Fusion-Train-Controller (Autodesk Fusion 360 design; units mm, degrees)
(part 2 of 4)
sketch "M4 preload adjuster" plane through (0, 0, 37.9) normal (0, 0, 1) x axis (1, 0, 0)
  circle C1 centre (12, -55) radius 2.2
extrude "Extrude6" cut sketch "M4 preload adjuster" along normal blind 14.2
work_plane "WorkPlane7" AlongDistance 37.9 ExtraOffset 0
sketch "Spring-side loaded retained M4 nut" plane through (0, 0, 37.9) normal (0, 0, 1) x axis (1, 0, 0)
  line L1 (14.1362, -51.3) -> (16.2724, -55)
  line L2 (9.8638, -51.3) -> (14.1362, -51.3)
  line L3 (7.7276, -55) -> (9.8638, -51.3)
  line L4 (9.8638, -58.7) -> (7.7276, -55)
  line L5 (14.1362, -58.7) -> (9.8638, -58.7)
  line L6 (16.2724, -55) -> (14.1362, -58.7)
extrude "Extrude7" cut sketch "Spring-side loaded retained M4 nut" along normal blind 3.5
work_plane "WorkPlane8" AlongDistance 37.9 ExtraOffset 0
sketch "Spring cup guide bolts" plane through (0, 0, 37.9) normal (0, 0, 1) x axis (1, 0, 0)
  circle C1 centre (5, -55) radius 1.7
extrude "Extrude8" cut sketch "Spring cup guide bolts" along normal blind 14.2
work_plane "WorkPlane9" AlongDistance 37.9 ExtraOffset 0
sketch "Spring cup guide bolts (1)" plane through (0, 0, 37.9) normal (0, 0, 1) x axis (1, 0, 0)
  circle C1 centre (19, -55) radius 1.7
extrude "Extrude9" cut sketch "Spring cup guide bolts (1)" along normal blind 14.2
work_plane "WorkPlane1" AlongDistance 1.5 ExtraOffset 0
sketch "Spring seat" plane through (1.5, 0, 0) normal (1, 0, 0) x axis (0, 0, -1)
  line L1 (-35, -49) -> (-35, -61)
  line L2 (-37, -49) -> (-35, -49)
  line L3 (-37, -61) -> (-37, -49)
  line L4 (-35, -61) -> (-37, -61)
extrude "Extrude1" new body sketch "Spring seat" along normal blind 21 bodies "P14 Captive spring cup"
work_plane "WorkPlane2" AlongDistance 27 ExtraOffset 0
sketch "Spring centering pilot" plane through (0, 0, 27) normal (0, 0, 1) x axis (1, 0, 0)
  circle C1 centre (12, -55) radius 2
extrude "Extrude2" add sketch "Spring centering pilot" along normal blind 8
work_plane "WorkPlane3" AlongDistance 34.9 ExtraOffset 0
sketch "Sliding guide clearance" plane through (0, 0, 34.9) normal (0, 0, 1) x axis (1, 0, 0)
  circle C1 centre (5, -55) radius 1.8
extrude "Extrude3" cut sketch "Sliding guide clearance" along normal blind 2.2
work_plane "WorkPlane4" AlongDistance 34.9 ExtraOffset 0
sketch "Sliding guide clearance (1)" plane through (0, 0, 34.9) normal (0, 0, 1) x axis (1, 0, 0)
  circle C1 centre (19, -55) radius 1.8
extrude "Extrude4" cut sketch "Sliding guide clearance (1)" along normal blind 2.2
work_plane "WorkPlane11" AlongDistance -18 ExtraOffset 0
sketch "Dedicated thick stop lug" plane through (-18, 0, 0) normal (1, 0, 0) x axis (0, 0, -1)
  line L1 (-72, 5) -> (-72, -5)
  line L2 (-95, 5) -> (-72, 5)
  line L3 (-95, -5) -> (-95, 5)
  line L4 (-72, -5) -> (-95, -5)
extrude "Extrude11" add sketch "Dedicated thick stop lug" along normal blind 11.5
work_plane "WorkPlane12" AlongDistance -18 ExtraOffset 0
sketch "Rounded stop contact" plane through (-18, 0, 0) normal (1, 0, 0) x axis (0, 0, -1)
  circle C1 centre (-95, 0) radius 5
extrude "Extrude12" add sketch "Rounded stop contact" along normal blind 11.5
work_plane "WorkPlane10" AlongDistance -36 ExtraOffset 0
sketch "Broad stop support ear" plane through (-36, 0, 0) normal (1, 0, 0) x axis (0, 0, -1)
  line L1 (-60, -20) -> (-60, -44)
  line L2 (-90, -20) -> (-60, -20)
  line L3 (-90, -44) -> (-90, -20)
  line L4 (-60, -44) -> (-90, -44)
extrude "Extrude10" add sketch "Broad stop support ear" along normal blind 12
work_plane "WorkPlane11" AlongDistance -24 ExtraOffset 0
sketch "Integrated steel-core end stop" plane through (-24, 0, 0) normal (1, 0, 0) x axis (0, 0, -1)
  circle C1 centre (-79.6754, -33.9652) radius 6
extrude "Extrude11" add sketch "Integrated steel-core end stop" along normal blind 15
work_plane "WorkPlane12" AlongDistance -36.1 ExtraOffset 0
sketch "M5 stop reinforcement bolt" plane through (-36.1, 0, 0) normal (1, 0, 0) x axis (0, 0, -1)
  circle C1 centre (-79.6754, -33.9652) radius 2.7
extrude "Extrude12" cut sketch "M5 stop reinforcement bolt" along normal blind 27.2
work_plane "WorkPlane13" AlongDistance -15.4 ExtraOffset 0
sketch "M5 captive stop nut" plane through (-15.4, 0, 0) normal (1, 0, 0) x axis (0, 0, -1)
  line L1 (-83.8754, -31.5403) -> (-79.6754, -29.1154)
  line L2 (-83.8754, -36.39) -> (-83.8754, -31.5403)
  line L3 (-79.6754, -38.8149) -> (-83.8754, -36.39)
  line L4 (-75.4754, -36.39) -> (-79.6754, -38.8149)
  line L5 (-75.4754, -31.5403) -> (-75.4754, -36.39)
  line L6 (-79.6754, -29.1154) -> (-75.4754, -31.5403)
extrude "Extrude13" cut sketch "M5 captive stop nut" along normal blind 6.5
work_plane "WorkPlane14" AlongDistance -36 ExtraOffset 0
sketch "Broad stop support ear (1)" plane through (-36, 0, 0) normal (1, 0, 0) x axis (0, 0, -1)
  line L1 (-60, 44) -> (-60, 20)
  line L2 (-90, 44) -> (-60, 44)
  line L3 (-90, 20) -> (-90, 44)
  line L4 (-60, 20) -> (-90, 20)
extrude "Extrude14" add sketch "Broad stop support ear (1)" along normal blind 12
work_plane "WorkPlane15" AlongDistance -24 ExtraOffset 0
sketch "Integrated steel-core end stop (1)" plane through (-24, 0, 0) normal (1, 0, 0) x axis (0, 0, -1)
  circle C1 centre (-79.6754, 33.9652) radius 6
extrude "Extrude15" add sketch "Integrated steel-core end stop (1)" along normal blind 15
work_plane "WorkPlane16" AlongDistance -36.1 ExtraOffset 0
sketch "M5 stop reinforcement bolt (1)" plane through (-36.1, 0, 0) normal (1, 0, 0) x axis (0, 0, -1)
  circle C1 centre (-79.6754, 33.9652) radius 2.7
extrude "Extrude16" cut sketch "M5 stop reinforcement bolt (1)" along normal blind 27.2
work_plane "WorkPlane17" AlongDistance -15.4 ExtraOffset 0
sketch "M5 captive stop nut (1)" plane through (-15.4, 0, 0) normal (1, 0, 0) x axis (0, 0, -1)
  line L1 (-83.8754, 36.39) -> (-79.6754, 38.8149)
  line L2 (-83.8754, 31.5403) -> (-83.8754, 36.39)
  line L3 (-79.6754, 29.1154) -> (-83.8754, 31.5403)
  line L4 (-75.4754, 31.5403) -> (-79.6754, 29.1154)
  line L5 (-75.4754, 36.39) -> (-75.4754, 31.5403)
  line L6 (-79.6754, 38.8149) -> (-75.4754, 36.39)
extrude "Extrude17" cut sketch "M5 captive stop nut (1)" along normal blind 6.5
work_plane "WorkPlane1" AlongDistance -24 ExtraOffset 0
sketch "H01 Pivot sleeve 8OD 5.2ID x48" plane through (-24, 0, 0) normal (1, 0, 0) x axis (0, 0, -1)
  circle C1 centre (-12, -35) radius 4
extrude "Extrude1" new body sketch "H01 Pivot sleeve 8OD 5.2ID x48" along normal blind 48 bodies "HARDWARE H01 Pivot sleeve 8OD 5.2ID x48"
work_plane "WorkPlane2" AlongDistance -24.1 ExtraOffset 0
sketch "Metal tube bore" plane through (-24.1, 0, 0) normal (1, 0, 0) x axis (0, 0, -1)
  circle C1 centre (-12, -35) radius 2.6
extrude "Extrude2" cut sketch "Metal tube bore" along normal blind 48.2
work_plane "WorkPlane1" AlongDistance 7 ExtraOffset 0
sketch "H02 Roller spacer 4OD 3.2ID x10" plane through (7, 0, 0) normal (1, 0, 0) x axis (0, 0, -1)
  circle C1 centre (-12, 0) radius 2
extrude "Extrude1" new body sketch "H02 Roller spacer 4OD 3.2ID x10" along normal blind 10 bodies "HARDWARE H02 Roller spacer 4OD 3.2ID x10"
work_plane "WorkPlane2" AlongDistance 6.9 ExtraOffset 0
sketch "Metal tube bore" plane through (6.9, 0, 0) normal (1, 0, 0) x axis (0, 0, -1)
  circle C1 centre (-12, 0) radius 1.6
extrude "Extrude2" cut sketch "Metal tube bore" along normal blind 10.2
work_plane "WorkPlane1" AlongDistance 18 ExtraOffset 0
sketch "Spring working envelope" plane through (0, 0, 18) normal (0, 0, 1) x axis (1, 0, 0)
  circle C1 centre (12, -55) radius 4
extrude "Extrude1" new body sketch "Spring working envelope" along normal blind 17 bodies "REFERENCE spring 8OD 5ID - 17 mm installed"
work_plane "WorkPlane2" AlongDistance 17.9 ExtraOffset 0
sketch "Spring internal clearance" plane through (0, 0, 17.9) normal (0, 0, 1) x axis (1, 0, 0)
  circle C1 centre (12, -55) radius 2.5
extrude "Extrude2" cut sketch "Spring internal clearance" along normal blind 17.2
work_plane "WorkPlane13" AlongDistance -24 ExtraOffset 0
sketch "Restore shaft socket through stop-lug root" plane through (-24, 0, 0) normal (1, 0, 0) x axis (0, 0, -1)
  line L1 (-69.6247, 6.65) -> (-60.3753, 6.65)
  arc A1 centre (-65, 0) radius 8.1 clockwise from (-60.3753, 6.65) to (-69.6247, 6.65)
extrude "Extrude13" cut sketch "Restore shaft socket through stop-lug root" along normal blind 48
work_plane "WorkPlane10" AlongDistance -24.1 ExtraOffset 0
sketch "Cam sweep clearance through crossblock" plane through (-24.1, 0, 0) normal (1, 0, 0) x axis (0, 0, -1)
  circle C1 centre (-65, 0) radius 51
extrude "Extrude10" cut sketch "Cam sweep clearance through crossblock" along normal blind 48.2
work_plane "WorkPlane10" AlongDistance 36 ExtraOffset 0
sketch "Rigid sensor carriage support" plane through (36, 0, 0) normal (1, 0, 0) x axis (0, 0, -1)
  line L1 (-49, -18) -> (-49, -28)
  line L2 (-81, -18) -> (-49, -18)
  line L3 (-81, -28) -> (-81, -18)
  line L4 (-49, -28) -> (-81, -28)
extrude "Extrude10" add sketch "Rigid sensor carriage support" along normal blind 44
work_plane "WorkPlane11" AlongDistance -28.1 ExtraOffset 0
sketch "M3 sensor carriage heat set" plane through (0, -28.1, 0) normal (0, 1, 0) x axis (1, 0, 0)
  circle C1 centre (74, -65) radius 2
extrude "Extrude11" cut sketch "M3 sensor carriage heat set" along normal blind 6.8
work_plane "WorkPlane12" AlongDistance 36 ExtraOffset 0
sketch "Rigid sensor carriage support (1)" plane through (36, 0, 0) normal (1, 0, 0) x axis (0, 0, -1)
  line L1 (-49, 28) -> (-49, 18)
  line L2 (-81, 28) -> (-49, 28)
  line L3 (-81, 18) -> (-81, 28)
  line L4 (-49, 18) -> (-81, 18)
extrude "Extrude12" add sketch "Rigid sensor carriage support (1)" along normal blind 44
work_plane "WorkPlane13" AlongDistance 21.3 ExtraOffset 0
sketch "M3 sensor carriage heat set (1)" plane through (0, 21.3, 0) normal (0, 1, 0) x axis (1, 0, 0)
  circle C1 centre (74, -65) radius 2
extrude "Extrude13" cut sketch "M3 sensor carriage heat set (1)" along normal blind 6.8
work_plane "WorkPlane1" AlongDistance 80 ExtraOffset 0
sketch "Replaceable sensor panel" plane through (80, 0, 0) normal (1, 0, 0) x axis (0, 0, -1)
  line L1 (-46, 33) -> (-46, -33)
  line L2 (-84, 33) -> (-46, 33)
  line L3 (-84, -33) -> (-84, 33)
  line L4 (-46, -33) -> (-84, -33)
extrude "Extrude1" new body sketch "Replaceable sensor panel" along normal blind 3 bodies "P16 Sliding replaceable RK097 mount"
work_plane "WorkPlane2" AlongDistance 68 ExtraOffset 0
sketch "Axially adjustable mounting ear" plane through (68, 0, 0) normal (1, 0, 0) x axis (0, 0, -1)
  line L1 (-58, -28) -> (-58, -33)
  line L2 (-72, -28) -> (-58, -28)
  line L3 (-72, -33) -> (-72, -28)
  line L4 (-58, -33) -> (-72, -33)
extrude "Extrude2" add sketch "Axially adjustable mounting ear" along normal blind 12.1
work_plane "WorkPlane3" AlongDistance -33.1 ExtraOffset 0
sketch "Ten mm axial adjustment slot" plane through (0, -33.1, 0) normal (0, 1, 0) x axis (1, 0, 0)
  line L1 (79, -63.3) -> (69, -63.3)
  line L2 (79, -66.7) -> (79, -63.3)
  line L3 (69, -66.7) -> (79, -66.7)
  line L4 (69, -63.3) -> (69, -66.7)
extrude "Extrude3" cut sketch "Ten mm axial adjustment slot" along normal blind 5.2
work_plane "WorkPlane4" AlongDistance -33.1 ExtraOffset 0
sketch "Rounded adjustment slot end" plane through (0, -33.1, 0) normal (0, 1, 0) x axis (1, 0, 0)
  circle C1 centre (69, -65) radius 1.7
extrude "Extrude4" cut sketch "Rounded adjustment slot end" along normal blind 5.2
work_plane "WorkPlane5" AlongDistance -33.1 ExtraOffset 0
sketch "Rounded adjustment slot end (1)" plane through (0, -33.1, 0) normal (0, 1, 0) x axis (1, 0, 0)
  circle C1 centre (79, -65) radius 1.7
extrude "Extrude5" cut sketch "Rounded adjustment slot end (1)" along normal blind 5.2
work_plane "WorkPlane6" AlongDistance 68 ExtraOffset 0
sketch "Axially adjustable mounting ear (1)" plane through (68, 0, 0) normal (1, 0, 0) x axis (0, 0, -1)
  line L1 (-58, 33) -> (-58, 28)
  line L2 (-72, 33) -> (-58, 33)
  line L3 (-72, 28) -> (-72, 33)
  line L4 (-58, 28) -> (-72, 28)
extrude "Extrude6" add sketch "Axially adjustable mounting ear (1)" along normal blind 12.1
work_plane "WorkPlane7" AlongDistance 27.9 ExtraOffset 0
sketch "Ten mm axial adjustment slot (1)" plane through (0, 27.9, 0) normal (0, 1, 0) x axis (1, 0, 0)
  line L1 (79, -63.3) -> (69, -63.3)
  line L2 (79, -66.7) -> (79, -63.3)
  line L3 (69, -66.7) -> (79, -66.7)
  line L4 (69, -63.3) -> (69, -66.7)
extrude "Extrude7" cut sketch "Ten mm axial adjustment slot (1)" along normal blind 5.2
work_plane "WorkPlane8" AlongDistance 27.9 ExtraOffset 0
sketch "Rounded adjustment slot end (2)" plane through (0, 27.9, 0) normal (0, 1, 0) x axis (1, 0, 0)
  circle C1 centre (69, -65) radius 1.7
extrude "Extrude8" cut sketch "Rounded adjustment slot end (2)" along normal blind 5.2
work_plane "WorkPlane9" AlongDistance 27.9 ExtraOffset 0
sketch "Rounded adjustment slot end (3)" plane through (0, 27.9, 0) normal (0, 1, 0) x axis (1, 0, 0)
  circle C1 centre (79, -65) radius 1.7
extrude "Extrude9" cut sketch "Rounded adjustment slot end (3)" along normal blind 5.2
work_plane "WorkPlane10" AlongDistance 79.9 ExtraOffset 0
sketch "Assumed RK097 M7 panel bushing" plane through (79.9, 0, 0) normal (1, 0, 0) x axis (0, 0, -1)
  circle C1 centre (-65, 0) radius 3.6
extrude "Extrude10" cut sketch "Assumed RK097 M7 panel bushing" along normal blind 3.2
work_plane "WorkPlane11" AlongDistance 79.9 ExtraOffset 0
sketch "Optional sensor body tie slot" plane through (79.9, 0, 0) normal (1, 0, 0) x axis (0, 0, -1)
  line L1 (-59, -7) -> (-59, -9)
  line L2 (-71, -7) -> (-59, -7)
  line L3 (-71, -9) -> (-71, -7)
  line L4 (-59, -9) -> (-71, -9)
extrude "Extrude11" cut sketch "Optional sensor body tie slot" along normal blind 3.2
work_plane "WorkPlane12" AlongDistance 79.9 ExtraOffset 0
sketch "Optional sensor body tie slot (1)" plane through (79.9, 0, 0) normal (1, 0, 0) x axis (0, 0, -1)
  line L1 (-59, 9) -> (-59, 7)
  line L2 (-71, 9) -> (-59, 9)
  line L3 (-71, 7) -> (-71, 9)
  line L4 (-59, 7) -> (-71, 7)
extrude "Extrude12" cut sketch "Optional sensor body tie slot (1)" along normal blind 3.2
work_plane "WorkPlane1" AlongDistance 40.5 ExtraOffset 0
sketch "Drive stub clamp hub" plane through (40.5, 0, 0) normal (1, 0, 0) x axis (0, 0, -1)
  circle C1 centre (-65, 0) radius 7
extrude "Extrude1" new body sketch "Drive stub clamp hub" along normal blind 10 bodies "P17 Shaft side floating coupling hub"
work_plane "WorkPlane2" AlongDistance 48 ExtraOffset 0
sketch "Oldham input flange" plane through (48, 0, 0) normal (1, 0, 0) x axis (0, 0, -1)
  circle C1 centre (-65, 0) radius 11
extrude "Extrude2" add sketch "Oldham input flange" along normal blind 2.5
work_plane "WorkPlane3" AlongDistance 50.5 ExtraOffset 0
sketch "Input sliding tongue" plane through (50.5, 0, 0) normal (1, 0, 0) x axis (0, 0, -1)
  line L1 (-63, 8) -> (-63, -8)
  line L2 (-67, 8) -> (-63, 8)
  line L3 (-67, -8) -> (-67, 8)
  line L4 (-63, -8) -> (-67, -8)
extrude "Extrude3" add sketch "Input sliding tongue" along normal blind 3.7
work_plane "WorkPlane4" AlongDistance 40.4 ExtraOffset 0
sketch "Drive stub socket" plane through (40.4, 0, 0) normal (1, 0, 0) x axis (0, 0, -1)
  circle C1 centre (-65, 0) radius 4.1
extrude "Extrude4" cut sketch "Drive stub socket" along normal blind 10.2
work_plane "WorkPlane5" AlongDistance 40.5 ExtraOffset 0
sketch "D socket key flat" plane through (40.5, 0, 0) normal (1, 0, 0) x axis (0, 0, -1)
  line L1 (-61, 4.2) -> (-61, 3.35)
  line L2 (-69, 4.2) -> (-61, 4.2)
  line L3 (-69, 3.35) -> (-69, 4.2)
  line L4 (-61, 3.35) -> (-69, 3.35)
extrude "Extrude5" add sketch "D socket key flat" along normal blind 10
work_plane "WorkPlane6" AlongDistance -7.1 ExtraOffset 0
sketch "M3 radial tapped plastic clamp pilot" plane through (0, -7.1, 0) normal (0, 1, 0) x axis (1, 0, 0)
  circle C1 centre (44.5, -65) radius 1.25
work_plane "WorkPlane1" AlongDistance 52 ExtraOffset 0
sketch "Floating misalignment disc" plane through (52, 0, 0) normal (1, 0, 0) x axis (0, 0, -1)
  circle C1 centre (-65, 0) radius 12
extrude "Extrude1" new body sketch "Floating misalignment disc" along normal blind 8 bodies "P18 Floating cross-slot coupling disc"
work_plane "WorkPlane2" AlongDistance 51.9 ExtraOffset 0
sketch "Input transverse sliding slot" plane through (51.9, 0, 0) normal (1, 0, 0) x axis (0, 0, -1)
  line L1 (-62.8, 13) -> (-62.8, -13)
  line L2 (-67.2, 13) -> (-62.8, 13)
  line L3 (-67.2, -13) -> (-67.2, 13)
  line L4 (-62.8, -13) -> (-67.2, -13)
work_plane "WorkPlane3" AlongDistance 57.5 ExtraOffset 0
sketch "Output perpendicular sliding slot" plane through (57.5, 0, 0) normal (1, 0, 0) x axis (0, 0, -1)
  line L1 (-52, 2.2) -> (-52, -2.2)
  line L2 (-78, 2.2) -> (-52, 2.2)
  line L3 (-78, -2.2) -> (-78, 2.2)
  line L4 (-52, -2.2) -> (-78, -2.2)
work_plane "WorkPlane1" AlongDistance 62 ExtraOffset 0
sketch "Replaceable sensor shaft clamp" plane through (62, 0, 0) normal (1, 0, 0) x axis (0, 0, -1)
  line L1 (-54, -0.2) -> (-54, -9)
  line L2 (-76, -0.2) -> (-54, -0.2)
  line L3 (-76, -9) -> (-76, -0.2)
  line L4 (-54, -9) -> (-76, -9)
extrude "Extrude1" new body sketch "Replaceable sensor shaft clamp" along normal blind 10 bodies "P19 RK097 clamp insert half"
work_plane "WorkPlane2" AlongDistance 57.8 ExtraOffset 0
sketch "Output Oldham tongue" plane through (57.8, 0, 0) normal (1, 0, 0) x axis (0, 0, -1)
  line L1 (-57, -0.2) -> (-57, -2)
  line L2 (-73, -0.2) -> (-57, -0.2)
  line L3 (-73, -2) -> (-73, -0.2)
  line L4 (-57, -2) -> (-73, -2)
extrude "Extrude2" add sketch "Output Oldham tongue" along normal blind 4.3
work_plane "WorkPlane3" AlongDistance 57.7 ExtraOffset 0
sketch "Assumed 6 mm sensor shaft bore" plane through (57.7, 0, 0) normal (1, 0, 0) x axis (0, 0, -1)
  circle C1 centre (-65, 0) radius 3.1
extrude "Extrude3" cut sketch "Assumed 6 mm sensor shaft bore" along normal blind 14.4
work_plane "WorkPlane4" AlongDistance -7.2 ExtraOffset 0
sketch "M3 clamp heat set" plane through (0, -7.2, 0) normal (0, 1, 0) x axis (1, 0, 0)
  circle C1 centre (67, -58) radius 2
extrude "Extrude4" cut sketch "M3 clamp heat set" along normal blind 7.1
work_plane "WorkPlane5" AlongDistance -7.2 ExtraOffset 0
sketch "M3 clamp heat set (1)" plane through (0, -7.2, 0) normal (0, 1, 0) x axis (1, 0, 0)
  circle C1 centre (67, -72) radius 2
extrude "Extrude5" cut sketch "M3 clamp heat set (1)" along normal blind 7.1
work_plane "WorkPlane1" AlongDistance 62 ExtraOffset 0
sketch "Replaceable sensor shaft clamp" plane through (62, 0, 0) normal (1, 0, 0) x axis (0, 0, -1)
  line L1 (-54, 9) -> (-54, 0.2)
  line L2 (-76, 9) -> (-54, 9)
  line L3 (-76, 0.2) -> (-76, 9)
  line L4 (-54, 0.2) -> (-76, 0.2)
extrude "Extrude1" new body sketch "Replaceable sensor shaft clamp" along normal blind 10 bodies "P20 RK097 clamp screw half"
work_plane "WorkPlane2" AlongDistance 57.8 ExtraOffset 0
sketch "Output Oldham tongue" plane through (57.8, 0, 0) normal (1, 0, 0) x axis (0, 0, -1)
  line L1 (-57, 2) -> (-57, 0.2)
  line L2 (-73, 2) -> (-57, 2)
  line L3 (-73, 0.2) -> (-73, 2)
  line L4 (-57, 0.2) -> (-73, 0.2)
extrude "Extrude2" add sketch "Output Oldham tongue" along normal blind 4.3
work_plane "WorkPlane3" AlongDistance 57.7 ExtraOffset 0
sketch "Assumed 6 mm sensor shaft bore" plane through (57.7, 0, 0) normal (1, 0, 0) x axis (0, 0, -1)
  circle C1 centre (-65, 0) radius 3.1
extrude "Extrude3" cut sketch "Assumed 6 mm sensor shaft bore" along normal blind 14.4
work_plane "WorkPlane4" AlongDistance 0.1 ExtraOffset 0
sketch "M3 clamp screw clearance" plane through (0, 0.1, 0) normal (0, 1, 0) x axis (1, 0, 0)
  circle C1 centre (67, -58) radius 1.7
extrude "Extrude4" cut sketch "M3 clamp screw clearance" along normal blind 9
work_plane "WorkPlane5" AlongDistance 0.1 ExtraOffset 0
sketch "M3 clamp screw clearance (1)" plane through (0, 0.1, 0) normal (0, 1, 0) x axis (1, 0, 0)
  circle C1 centre (67, -72) radius 1.7
extrude "Extrude5" cut sketch "M3 clamp screw clearance (1)" along normal blind 9
work_plane "WorkPlane1" AlongDistance 83 ExtraOffset 0
sketch "Unmeasured RK097 body clearance" plane through (83, 0, 0) normal (1, 0, 0) x axis (0, 0, -1)
  line L1 (-60.25, 4.75) -> (-60.25, -4.75)
  line L2 (-69.75, 4.75) -> (-60.25, 4.75)
  line L3 (-69.75, -4.75) -> (-69.75, 4.75)
  line L4 (-60.25, -4.75) -> (-69.75, -4.75)
extrude "Extrude1" new body sketch "Unmeasured RK097 body clearance" along normal blind 14 bodies "REFERENCE RK097 ASSUMED envelope - verify actual part"
work_plane "WorkPlane2" AlongDistance 76 ExtraOffset 0
sketch "Assumed M7 mounting bushing" plane through (76, 0, 0) normal (1, 0, 0) x axis (0, 0, -1)
  circle C1 centre (-65, 0) radius 3.5
extrude "Extrude2" add sketch "Assumed M7 mounting bushing" along normal blind 7
work_plane "WorkPlane3" AlongDistance 64 ExtraOffset 0
sketch "Assumed 6 mm shaft" plane through (64, 0, 0) normal (1, 0, 0) x axis (0, 0, -1)
  circle C1 centre (-65, 0) radius 3
extrude "Extrude3" add sketch "Assumed 6 mm shaft" along normal blind 12
work_plane "WorkPlane7" AlongDistance 40.5 ExtraOffset 0
sketch "Pinch clamp reinforcement" plane through (40.5, 0, 0) normal (1, 0, 0) x axis (0, 0, -1)
  line L1 (-69, 9) -> (-69, -9)
  line L2 (-78, 9) -> (-69, 9)
  line L3 (-78, -9) -> (-78, 9)
  line L4 (-69, -9) -> (-78, -9)
extrude "Extrude7" add sketch "Pinch clamp reinforcement" along normal blind 10
work_plane "WorkPlane8" AlongDistance 40.4 ExtraOffset 0
sketch "Compliant clamp split" plane through (40.4, 0, 0) normal (1, 0, 0) x axis (0, 0, -1)
  line L1 (-65, 0.2) -> (-65, -0.2)
  line L2 (-79, 0.2) -> (-65, 0.2)
  line L3 (-79, -0.2) -> (-79, 0.2)
  line L4 (-65, -0.2) -> (-79, -0.2)
extrude "Extrude8" cut sketch "Compliant clamp split" along normal blind 10.2
work_plane "WorkPlane9" AlongDistance -7.2 ExtraOffset 0
sketch "M3 pinch clamp heat set" plane through (0, -7.2, 0) normal (0, 1, 0) x axis (1, 0, 0)
  circle C1 centre (45.5, -73) radius 2
extrude "Extrude9" cut sketch "M3 pinch clamp heat set" along normal blind 7.1
work_plane "WorkPlane10" AlongDistance 0.1 ExtraOffset 0
sketch "M3 pinch clamp screw clearance" plane through (0, 0.1, 0) normal (0, 1, 0) x axis (1, 0, 0)
  circle C1 centre (45.5, -73) radius 1.7
extrude "Extrude10" cut sketch "M3 pinch clamp screw clearance" along normal blind 9
work_plane "WorkPlane5" AlongDistance 34.9 ExtraOffset 0
sketch "Smooth guide tube clearance" plane through (0, 0, 34.9) normal (0, 0, 1) x axis (1, 0, 0)
  circle C1 centre (5, -55) radius 2.2
extrude "Extrude5" cut sketch "Smooth guide tube clearance" along normal blind 2.2
work_plane "WorkPlane6" AlongDistance 34.9 ExtraOffset 0
sketch "Smooth guide tube clearance (1)" plane through (0, 0, 34.9) normal (0, 0, 1) x axis (1, 0, 0)
  circle C1 centre (19, -55) radius 2.2
extrude "Extrude6" cut sketch "Smooth guide tube clearance (1)" along normal blind 2.2
work_plane "WorkPlane1" AlongDistance -24 ExtraOffset 0
sketch "Controlled follower end float" plane through (-24, 0, 0) normal (1, 0, 0) x axis (0, 0, -1)
  circle C1 centre (-12, -35) radius 6
extrude "Extrude1" new body sketch "Controlled follower end float" along normal blind 27.8 bodies "P21 Follower left axial spacer"
work_plane "WorkPlane2" AlongDistance -24.1 ExtraOffset 0
sketch "Pivot sleeve running clearance" plane through (-24.1, 0, 0) normal (1, 0, 0) x axis (0, 0, -1)
  circle C1 centre (-12, -35) radius 4.2
extrude "Extrude2" cut sketch "Pivot sleeve running clearance" along normal blind 28
work_plane "WorkPlane1" AlongDistance 20.2 ExtraOffset 0
sketch "Controlled follower end float" plane through (20.2, 0, 0) normal (1, 0, 0) x axis (0, 0, -1)
  circle C1 centre (-12, -35) radius 6
extrude "Extrude1" new body sketch "Controlled follower end float" along normal blind 3.8 bodies "P22 Follower right axial spacer"
work_plane "WorkPlane2" AlongDistance 20.1 ExtraOffset 0
sketch "Pivot sleeve running clearance" plane through (20.1, 0, 0) normal (1, 0, 0) x axis (0, 0, -1)
  circle C1 centre (-12, -35) radius 4.2
extrude "Extrude2" cut sketch "Pivot sleeve running clearance" along normal blind 4
work_plane "WorkPlane1" AlongDistance 32 ExtraOffset 0
sketch "Guide bolt compression tube" plane through (0, 0, 32) normal (0, 0, 1) x axis (1, 0, 0)
  circle C1 centre (5, -55) radius 2
extrude "Extrude1" new body sketch "Guide bolt compression tube" along normal blind 6 bodies "HARDWARE Guide tube 4OD 3.2ID x6 at 5"
work_plane "WorkPlane2" AlongDistance 31.9 ExtraOffset 0
sketch "M3 guide shank" plane through (0, 0, 31.9) normal (0, 0, 1) x axis (1, 0, 0)
  circle C1 centre (5, -55) radius 1.6
extrude "Extrude2" cut sketch "M3 guide shank" along normal blind 6.2
work_plane "WorkPlane1" AlongDistance 32 ExtraOffset 0
sketch "Guide bolt compression tube" plane through (0, 0, 32) normal (0, 0, 1) x axis (1, 0, 0)
  circle C1 centre (19, -55) radius 2
extrude "Extrude1" new body sketch "Guide bolt compression tube" along normal blind 6 bodies "HARDWARE Guide tube 4OD 3.2ID x6 at 19"
work_plane "WorkPlane2" AlongDistance 31.9 ExtraOffset 0
sketch "M3 guide shank" plane through (0, 0, 31.9) normal (0, 0, 1) x axis (1, 0, 0)
  circle C1 centre (19, -55) radius 1.6
extrude "Extrude2" cut sketch "M3 guide shank" along normal blind 6.2
work_plane "WorkPlane1" AlongDistance -39.35 ExtraOffset 0
sketch "Main shaft cap M3x8" plane through (-39.35, 0, 0) normal (1, 0, 0) x axis (0, 0, -1)
  circle C1 centre (-65, 0) radius 1.5
extrude "Extrude1" new body sketch "Main shaft cap M3x8" along normal blind 8 bodies "HARDWARE Main shaft cap M3x8"
work_plane "WorkPlane2" AlongDistance -41 ExtraOffset 0
sketch "Button head" plane through (-41, 0, 0) normal (1, 0, 0) x axis (0, 0, -1)
  circle C1 centre (-65, 0) radius 2.85
extrude "Extrude2" add sketch "Button head" along normal blind 1.65
work_plane "WorkPlane1" AlongDistance 2 ExtraOffset 0
sketch "Cam fastener M3x10 -45" plane through (2, 0, 0) normal (1, 0, 0) x axis (0, 0, -1)
  circle C1 centre (-39.5442, 25.4558) radius 1.5
extrude "Extrude1" new body sketch "Cam fastener M3x10 -45" along normal blind 10 bodies "HARDWARE Cam fastener M3x10 -45"
work_plane "WorkPlane2" AlongDistance 12 ExtraOffset 0
sketch "Button head" plane through (12, 0, 0) normal (1, 0, 0) x axis (0, 0, -1)
  circle C1 centre (-39.5442, 25.4558) radius 2.85
extrude "Extrude2" add sketch "Button head" along normal blind 1.65
work_plane "WorkPlane1" AlongDistance 2 ExtraOffset 0
sketch "Cam fastener M3x10 0" plane through (2, 0, 0) normal (1, 0, 0) x axis (0, 0, -1)
  circle C1 centre (-29, 0) radius 1.5
extrude "Extrude1" new body sketch "Cam fastener M3x10 0" along normal blind 10 bodies "HARDWARE Cam fastener M3x10 0"
work_plane "WorkPlane2" AlongDistance 12 ExtraOffset 0
sketch "Button head" plane through (12, 0, 0) normal (1, 0, 0) x axis (0, 0, -1)
  circle C1 centre (-29, 0) radius 2.85
extrude "Extrude2" add sketch "Button head" along normal blind 1.65
work_plane "WorkPlane1" AlongDistance 2 ExtraOffset 0
sketch "Cam fastener M3x10 45" plane through (2, 0, 0) normal (1, 0, 0) x axis (0, 0, -1)
  circle C1 centre (-39.5442, -25.4558) radius 1.5
extrude "Extrude1" new body sketch "Cam fastener M3x10 45" along normal blind 10 bodies "HARDWARE Cam fastener M3x10 45"
work_plane "WorkPlane2" AlongDistance 12 ExtraOffset 0
sketch "Button head" plane through (12, 0, 0) normal (1, 0, 0) x axis (0, 0, -1)
  circle C1 centre (-39.5442, -25.4558) radius 2.85
extrude "Extrude2" add sketch "Button head" along normal blind 1.65
work_plane "WorkPlane1" AlongDistance -12.5 ExtraOffset 0
sketch "Grip fastener M3x25 180" plane through (-12.5, 0, 0) normal (1, 0, 0) x axis (0, 0, -1)
  circle C1 centre (-180, 0) radius 1.5
extrude "Extrude1" new body sketch "Grip fastener M3x25 180" along normal blind 25 bodies "HARDWARE Grip fastener M3x25 180"
work_plane "WorkPlane2" AlongDistance 12.5 ExtraOffset 0
sketch "Button head" plane through (12.5, 0, 0) normal (1, 0, 0) x axis (0, 0, -1)
  circle C1 centre (-180, 0) radius 2.85
extrude "Extrude2" add sketch "Button head" along normal blind 1.65
work_plane "WorkPlane1" AlongDistance -12.5 ExtraOffset 0
sketch "Grip fastener M3x25 190" plane through (-12.5, 0, 0) normal (1, 0, 0) x axis (0, 0, -1)
  circle C1 centre (-190, 0) radius 1.5
extrude "Extrude1" new body sketch "Grip fastener M3x25 190" along normal blind 25 bodies "HARDWARE Grip fastener M3x25 190"
work_plane "WorkPlane2" AlongDistance 12.5 ExtraOffset 0
sketch "Button head" plane through (12.5, 0, 0) normal (1, 0, 0) x axis (0, 0, -1)
  circle C1 centre (-190, 0) radius 2.85
extrude "Extrude2" add sketch "Button head" along normal blind 1.65
work_plane "WorkPlane1" AlongDistance 0 ExtraOffset 0
sketch "Roller axle M3x20" plane through (0, 0, 0) normal (1, 0, 0) x axis (0, 0, -1)
  circle C1 centre (-12, 0) radius 1.5
extrude "Extrude1" new body sketch "Roller axle M3x20" along normal blind 20 bodies "HARDWARE Roller axle M3x20"
work_plane "WorkPlane2" AlongDistance 20 ExtraOffset 0
sketch "Button head" plane through (20, 0, 0) normal (1, 0, 0) x axis (0, 0, -1)
  circle C1 centre (-12, 0) radius 2.85
extrude "Extrude2" add sketch "Button head" along normal blind 1.65
work_plane "WorkPlane1" AlongDistance 3.1 ExtraOffset 0
sketch "Roller axle M3 nut" plane through (3.1, 0, 0) normal (1, 0, 0) x axis (0, 0, -1)
  line L1 (-14.75, 1.5877) -> (-12, 3.1754)
  line L2 (-14.75, -1.5877) -> (-14.75, 1.5877)
  line L3 (-12, -3.1754) -> (-14.75, -1.5877)
  line L4 (-9.25, -1.5877) -> (-12, -3.1754)
  line L5 (-9.25, 1.5877) -> (-9.25, -1.5877)
  line L6 (-12, 3.1754) -> (-9.25, 1.5877)
extrude "Extrude1" new body sketch "Roller axle M3 nut" along normal blind 2.4 bodies "HARDWARE Roller axle M3 nut"
work_plane "WorkPlane2" AlongDistance 3 ExtraOffset 0
sketch "Thread envelope" plane through (3, 0, 0) normal (1, 0, 0) x axis (0, 0, -1)
  circle C1 centre (-12, 0) radius 1.5
extrude "Extrude2" cut sketch "Thread envelope" along normal blind 2.6
work_plane "WorkPlane1" AlongDistance 38.2 ExtraOffset 0
sketch "Retained preload M4 nut" plane through (0, 0, 38.2) normal (0, 0, 1) x axis (1, 0, 0)
  line L1 (14.0207, -51.5) -> (16.0415, -55)
  line L2 (9.9793, -51.5) -> (14.0207, -51.5)
  line L3 (7.9585, -55) -> (9.9793, -51.5)
  line L4 (9.9793, -58.5) -> (7.9585, -55)
  line L5 (14.0207, -58.5) -> (9.9793, -58.5)
  line L6 (16.0415, -55) -> (14.0207, -58.5)
extrude "Extrude1" new body sketch "Retained preload M4 nut" along normal blind 3.2 bodies "HARDWARE Retained preload M4 nut"
work_plane "WorkPlane2" AlongDistance 38.1 ExtraOffset 0
sketch "Thread envelope" plane through (0, 0, 38.1) normal (0, 0, 1) x axis (1, 0, 0)
  circle C1 centre (12, -55) radius 2
extrude "Extrude2" cut sketch "Thread envelope" along normal blind 3.4
work_plane "WorkPlane1" AlongDistance -6.5 ExtraOffset 0
sketch "Coupler clamp M3x16 (45.5, 73)" plane through (0, -6.5, 0) normal (0, 1, 0) x axis (1, 0, 0)
  circle C1 centre (45.5, -73) radius 1.5
extrude "Extrude1" new body sketch "Coupler clamp M3x16 (45.5, 73)" along normal blind 16 bodies "HARDWARE Coupler clamp M3x16 (45.5, 73)"
work_plane "WorkPlane2" AlongDistance 9.5 ExtraOffset 0
sketch "Button head" plane through (0, 9.5, 0) normal (0, 1, 0) x axis (1, 0, 0)
  circle C1 centre (45.5, -73) radius 2.85
extrude "Extrude2" add sketch "Button head" along normal blind 1.65
work_plane "WorkPlane1" AlongDistance 9 ExtraOffset 0
sketch "Coupler clamp washer (45.5, 73)" plane through (0, 9, 0) normal (0, 1, 0) x axis (1, 0, 0)
  circle C1 centre (45.5, -73) radius 3.5
extrude "Extrude1" new body sketch "Coupler clamp washer (45.5, 73)" along normal blind 0.5 bodies "HARDWARE Coupler clamp washer (45.5, 73)"
work_plane "WorkPlane2" AlongDistance 8.9 ExtraOffset 0
sketch "Washer clearance" plane through (0, 8.9, 0) normal (0, 1, 0) x axis (1, 0, 0)
  circle C1 centre (45.5, -73) radius 1.7
extrude "Extrude2" cut sketch "Washer clearance" along normal blind 0.7
work_plane "WorkPlane1" AlongDistance -6.5 ExtraOffset 0
sketch "Coupler clamp M3x16 (67, 58)" plane through (0, -6.5, 0) normal (0, 1, 0) x axis (1, 0, 0)
  circle C1 centre (67, -58) radius 1.5
extrude "Extrude1" new body sketch "Coupler clamp M3x16 (67, 58)" along normal blind 16 bodies "HARDWARE Coupler clamp M3x16 (67, 58)"
work_plane "WorkPlane2" AlongDistance 9.5 ExtraOffset 0
sketch "Button head" plane through (0, 9.5, 0) normal (0, 1, 0) x axis (1, 0, 0)
  circle C1 centre (67, -58) radius 2.85
extrude "Extrude2" add sketch "Button head" along normal blind 1.65
work_plane "WorkPlane1" AlongDistance 9 ExtraOffset 0
sketch "Coupler clamp washer (67, 58)" plane through (0, 9, 0) normal (0, 1, 0) x axis (1, 0, 0)
  circle C1 centre (67, -58) radius 3.5
extrude "Extrude1" new body sketch "Coupler clamp washer (67, 58)" along normal blind 0.5 bodies "HARDWARE Coupler clamp washer (67, 58)"
work_plane "WorkPlane2" AlongDistance 8.9 ExtraOffset 0
sketch "Washer clearance" plane through (0, 8.9, 0) normal (0, 1, 0) x axis (1, 0, 0)
  circle C1 centre (67, -58) radius 1.7
extrude "Extrude2" cut sketch "Washer clearance" along normal blind 0.7
work_plane "WorkPlane1" AlongDistance -6.5 ExtraOffset 0
sketch "Coupler clamp M3x16 (67, 72)" plane through (0, -6.5, 0) normal (0, 1, 0) x axis (1, 0, 0)
  circle C1 centre (67, -72) radius 1.5
extrude "Extrude1" new body sketch "Coupler clamp M3x16 (67, 72)" along normal blind 16 bodies "HARDWARE Coupler clamp M3x16 (67, 72)"
work_plane "WorkPlane2" AlongDistance 9.5 ExtraOffset 0
sketch "Button head" plane through (0, 9.5, 0) normal (0, 1, 0) x axis (1, 0, 0)
  circle C1 centre (67, -72) radius 2.85
extrude "Extrude2" add sketch "Button head" along normal blind 1.65
work_plane "WorkPlane1" AlongDistance 9 ExtraOffset 0
sketch "Coupler clamp washer (67, 72)" plane through (0, 9, 0) normal (0, 1, 0) x axis (1, 0, 0)
  circle C1 centre (67, -72) radius 3.5
extrude "Extrude1" new body sketch "Coupler clamp washer (67, 72)" along normal blind 0.5 bodies "HARDWARE Coupler clamp washer (67, 72)"
work_plane "WorkPlane2" AlongDistance 8.9 ExtraOffset 0
sketch "Washer clearance" plane through (0, 8.9, 0) normal (0, 1, 0) x axis (1, 0, 0)
  circle C1 centre (67, -72) radius 1.7
extrude "Extrude2" cut sketch "Washer clearance" along normal blind 0.7
work_plane "WorkPlane1" AlongDistance -33.5 ExtraOffset 0
sketch "RK097 carriage M3x12 -1" plane through (0, -33.5, 0) normal (0, 1, 0) x axis (1, 0, 0)
  circle C1 centre (74, -65) radius 1.5
extrude "Extrude1" new body sketch "RK097 carriage M3x12 -1" along normal blind 12 bodies "HARDWARE RK097 carriage M3x12 -1"
work_plane "WorkPlane2" AlongDistance -35.15 ExtraOffset 0
sketch "Button head" plane through (0, -35.15, 0) normal (0, 1, 0) x axis (1, 0, 0)
  circle C1 centre (74, -65) radius 2.85
extrude "Extrude2" add sketch "Button head" along normal blind 1.65
work_plane "WorkPlane1" AlongDistance -33.5 ExtraOffset 0
sketch "RK097 carriage washer -1" plane through (0, -33.5, 0) normal (0, 1, 0) x axis (1, 0, 0)
  circle C1 centre (74, -65) radius 3.5
extrude "Extrude1" new body sketch "RK097 carriage washer -1" along normal blind 0.5 bodies "HARDWARE RK097 carriage washer -1"
work_plane "WorkPlane2" AlongDistance -33.6 ExtraOffset 0
sketch "Washer clearance" plane through (0, -33.6, 0) normal (0, 1, 0) x axis (1, 0, 0)
  circle C1 centre (74, -65) radius 1.7
extrude "Extrude2" cut sketch "Washer clearance" along normal blind 0.7
work_plane "WorkPlane1" AlongDistance 21.5 ExtraOffset 0
sketch "RK097 carriage M3x12 1" plane through (0, 21.5, 0) normal (0, 1, 0) x axis (1, 0, 0)
  circle C1 centre (74, -65) radius 1.5
extrude "Extrude1" new body sketch "RK097 carriage M3x12 1" along normal blind 12 bodies "HARDWARE RK097 carriage M3x12 1"
work_plane "WorkPlane2" AlongDistance 33.5 ExtraOffset 0
sketch "Button head" plane through (0, 33.5, 0) normal (0, 1, 0) x axis (1, 0, 0)
  circle C1 centre (74, -65) radius 2.85
extrude "Extrude2" add sketch "Button head" along normal blind 1.65
work_plane "WorkPlane1" AlongDistance 33 ExtraOffset 0
sketch "RK097 carriage washer 1" plane through (0, 33, 0) normal (0, 1, 0) x axis (1, 0, 0)
  circle C1 centre (74, -65) radius 3.5
extrude "Extrude1" new body sketch "RK097 carriage washer 1" along normal blind 0.5 bodies "HARDWARE RK097 carriage washer 1"
work_plane "WorkPlane2" AlongDistance 32.9 ExtraOffset 0
sketch "Washer clearance" plane through (0, 32.9, 0) normal (0, 1, 0) x axis (1, 0, 0)
  circle C1 centre (74, -65) radius 1.7
extrude "Extrude2" cut sketch "Washer clearance" along normal blind 0.7
work_plane "WorkPlane1" AlongDistance 79.5 ExtraOffset 0
sketch "RK097 assumed M7 washer" plane through (79.5, 0, 0) normal (1, 0, 0) x axis (0, 0, -1)
  circle C1 centre (-65, 0) radius 6
extrude "Extrude1" new body sketch "RK097 assumed M7 washer" along normal blind 0.5 bodies "HARDWARE RK097 assumed M7 washer"
work_plane "WorkPlane2" AlongDistance 79.4 ExtraOffset 0
sketch "Washer clearance" plane through (79.4, 0, 0) normal (1, 0, 0) x axis (0, 0, -1)
  circle C1 centre (-65, 0) radius 3.6
extrude "Extrude2" cut sketch "Washer clearance" along normal blind 0.7
work_plane "WorkPlane1" AlongDistance 77.5 ExtraOffset 0
sketch "RK097 assumed M7 nut" plane through (77.5, 0, 0) normal (1, 0, 0) x axis (0, 0, -1)
  line L1 (-70.5, 3.1754) -> (-65, 6.3509)
  line L2 (-70.5, -3.1754) -> (-70.5, 3.1754)
  line L3 (-65, -6.3509) -> (-70.5, -3.1754)
  line L4 (-59.5, -3.1754) -> (-65, -6.3509)
  line L5 (-59.5, 3.1754) -> (-59.5, -3.1754)
  line L6 (-65, 6.3509) -> (-59.5, 3.1754)
extrude "Extrude1" new body sketch "RK097 assumed M7 nut" along normal blind 2 bodies "HARDWARE RK097 assumed M7 nut"
work_plane "WorkPlane2" AlongDistance 77.4 ExtraOffset 0
sketch "Thread envelope" plane through (77.4, 0, 0) normal (1, 0, 0) x axis (0, 0, -1)
  circle C1 centre (-65, 0) radius 3.5
extrude "Extrude2" cut sketch "Thread envelope" along normal blind 2.2
work_plane "WorkPlane14" AlongDistance 23.9 ExtraOffset 0
sketch "Cam lateral service opening" plane through (23.9, 0, 0) normal (1, 0, 0) x axis (0, 0, -1)
  line L1 (-42.2047, 46.7373) -> (-43.8497, 47.5044)
  line L2 (-40.5875, 45.9133) -> (-42.2047, 46.7373)
  line L3 (-39, 45.0333) -> (-40.5875, 45.9133)
  line L4 (-37.4442, 44.0985) -> (-39, 45.0333)
  line L5 (-35.922, 43.11) -> (-37.4442, 44.0985)
  line L6 (-34.4352, 42.0689) -> (-35.922, 43.11)
  line L7 (-32.9856, 40.9766) -> (-34.4352, 42.0689)
  line L8 (-31.575, 39.8343) -> (-32.9856, 40.9766)
  line L9 (-30.2052, 38.6435) -> (-31.575, 39.8343)
  line L10 (-28.8778, 37.4057) -> (-30.2052, 38.6435)
  line L11 (-27.5943, 36.1222) -> (-28.8778, 37.4057)
  line L12 (-26.3565, 34.7948) -> (-27.5943, 36.1222)
  line L13 (-25.1657, 33.425) -> (-26.3565, 34.7948)
  line L14 (-24.0234, 32.0144) -> (-25.1657, 33.425)
  line L15 (-22.9311, 30.5648) -> (-24.0234, 32.0144)
  line L16 (-21.89, 29.078) -> (-22.9311, 30.5648)
  line L17 (-20.9015, 27.5558) -> (-21.89, 29.078)
  line L18 (-19.9667, 26) -> (-20.9015, 27.5558)
  line L19 (-19.0867, 24.4125) -> (-19.9667, 26)
  line L20 (-18.2627, 22.7953) -> (-19.0867, 24.4125)
  line L21 (-17.4956, 21.1503) -> (-18.2627, 22.7953)
  line L22 (-16.7864, 19.4795) -> (-17.4956, 21.1503)
  line L23 (-16.136, 17.785) -> (-16.7864, 19.4795)
  line L24 (-15.5451, 16.0689) -> (-16.136, 17.785)
  line L25 (-15.0144, 14.3331) -> (-15.5451, 16.0689)
  line L26 (-14.5446, 12.5799) -> (-15.0144, 14.3331)
  line L27 (-14.1363, 10.8114) -> (-14.5446, 12.5799)
  line L28 (-13.79, 9.0297) -> (-14.1363, 10.8114)
  line L29 (-13.5061, 7.237) -> (-13.79, 9.0297)
  line L30 (-13.2849, 5.4355) -> (-13.5061, 7.237)
  line L31 (-13.1267, 3.6273) -> (-13.2849, 5.4355)
  line L32 (-13.0317, 1.8148) -> (-13.1267, 3.6273)
  line L33 (-13, 0) -> (-13.0317, 1.8148)
  line L34 (-13.0317, -1.8148) -> (-13, 0)
  line L35 (-13.1267, -3.6273) -> (-13.0317, -1.8148)
  line L36 (-13.2849, -5.4355) -> (-13.1267, -3.6273)
  line L37 (-13.5061, -7.237) -> (-13.2849, -5.4355)
  line L38 (-13.79, -9.0297) -> (-13.5061, -7.237)
  line L39 (-14.1363, -10.8114) -> (-13.79, -9.0297)
  line L40 (-14.5446, -12.5799) -> (-14.1363, -10.8114)
  line L41 (-15.0144, -14.3331) -> (-14.5446, -12.5799)
  line L42 (-15.5451, -16.0689) -> (-15.0144, -14.3331)
  line L43 (-16.136, -17.785) -> (-15.5451, -16.0689)
  line L44 (-16.7864, -19.4795) -> (-16.136, -17.785)
  line L45 (-17.4956, -21.1503) -> (-16.7864, -19.4795)
  line L46 (-18.2627, -22.7953) -> (-17.4956, -21.1503)
  line L47 (-19.0867, -24.4125) -> (-18.2627, -22.7953)
  line L48 (-19.9667, -26) -> (-19.0867, -24.4125)
  line L49 (-20.9015, -27.5558) -> (-19.9667, -26)
  line L50 (-21.89, -29.078) -> (-20.9015, -27.5558)
  line L51 (-22.9311, -30.5648) -> (-21.89, -29.078)
  line L52 (-24.0234, -32.0144) -> (-22.9311, -30.5648)
  line L53 (-25.1657, -33.425) -> (-24.0234, -32.0144)
  line L54 (-26.3565, -34.7948) -> (-25.1657, -33.425)
  line L55 (-27.5943, -36.1222) -> (-26.3565, -34.7948)
  line L56 (-28.8778, -37.4057) -> (-27.5943, -36.1222)
  line L57 (-30.2052, -38.6435) -> (-28.8778, -37.4057)
  line L58 (-31.575, -39.8343) -> (-30.2052, -38.6435)
  line L59 (-32.9856, -40.9766) -> (-31.575, -39.8343)
  line L60 (-34.4352, -42.0689) -> (-32.9856, -40.9766)
  line L61 (-35.922, -43.11) -> (-34.4352, -42.0689)
  line L62 (-37.4442, -44.0985) -> (-35.922, -43.11)
  line L63 (-39, -45.0333) -> (-37.4442, -44.0985)
  line L64 (-40.5875, -45.9133) -> (-39, -45.0333)
  line L65 (-42.2047, -46.7373) -> (-40.5875, -45.9133)
  line L66 (-43.8497, -47.5044) -> (-42.2047, -46.7373)
  line L67 (-54.4248, -23.7522) -> (-43.8497, -47.5044)
  line L68 (-53.6024, -23.3686) -> (-54.4248, -23.7522)
  line L69 (-52.7937, -22.9566) -> (-53.6024, -23.3686)
  line L70 (-52, -22.5167) -> (-52.7937, -22.9566)
  line L71 (-51.2221, -22.0493) -> (-52, -22.5167)
  line L72 (-50.461, -21.555) -> (-51.2221, -22.0493)
  line L73 (-49.7176, -21.0344) -> (-50.461, -21.555)
  line L74 (-48.9928, -20.4883) -> (-49.7176, -21.0344)
  line L75 (-48.2875, -19.9172) -> (-48.9928, -20.4883)
  line L76 (-47.6026, -19.3218) -> (-48.2875, -19.9172)
  line L77 (-46.9389, -18.7028) -> (-47.6026, -19.3218)
  line L78 (-46.2972, -18.0611) -> (-46.9389, -18.7028)
  line L79 (-45.6782, -17.3974) -> (-46.2972, -18.0611)
  line L80 (-45.0828, -16.7125) -> (-45.6782, -17.3974)
  line L81 (-44.5117, -16.0072) -> (-45.0828, -16.7125)
  line L82 (-43.9656, -15.2824) -> (-44.5117, -16.0072)
  line L83 (-43.445, -14.539) -> (-43.9656, -15.2824)
  line L84 (-42.9507, -13.7779) -> (-43.445, -14.539)
  line L85 (-42.4833, -13) -> (-42.9507, -13.7779)
  line L86 (-42.0434, -12.2063) -> (-42.4833, -13)
  line L87 (-41.6314, -11.3976) -> (-42.0434, -12.2063)
  line L88 (-41.2478, -10.5752) -> (-41.6314, -11.3976)
  line L89 (-40.8932, -9.7398) -> (-41.2478, -10.5752)
  line L90 (-40.568, -8.8925) -> (-40.8932, -9.7398)
  line L91 (-40.2725, -8.0344) -> (-40.568, -8.8925)
  line L92 (-40.0072, -7.1666) -> (-40.2725, -8.0344)
  line L93 (-39.7723, -6.29) -> (-40.0072, -7.1666)
  line L94 (-39.5682, -5.4057) -> (-39.7723, -6.29)
  line L95 (-39.395, -4.5149) -> (-39.5682, -5.4057)
  line L96 (-39.253, -3.6185) -> (-39.395, -4.5149)
  line L97 (-39.1424, -2.7177) -> (-39.253, -3.6185)
  line L98 (-39.0633, -1.8137) -> (-39.1424, -2.7177)
  line L99 (-39.0158, -0.9074) -> (-39.0633, -1.8137)
  line L100 (-39, 0) -> (-39.0158, -0.9074)
  line L101 (-39.0158, 0.9074) -> (-39, 0)
  line L102 (-39.0633, 1.8137) -> (-39.0158, 0.9074)
  line L103 (-39.1424, 2.7177) -> (-39.0633, 1.8137)
  line L104 (-39.253, 3.6185) -> (-39.1424, 2.7177)
  line L105 (-39.395, 4.5149) -> (-39.253, 3.6185)
  line L106 (-39.5682, 5.4057) -> (-39.395, 4.5149)
  line L107 (-39.7723, 6.29) -> (-39.5682, 5.4057)
  line L108 (-40.0072, 7.1666) -> (-39.7723, 6.29)
  line L109 (-40.2725, 8.0344) -> (-40.0072, 7.1666)
  line L110 (-40.568, 8.8925) -> (-40.2725, 8.0344)
  line L111 (-40.8932, 9.7398) -> (-40.568, 8.8925)
  line L112 (-41.2478, 10.5752) -> (-40.8932, 9.7398)
  line L113 (-41.6314, 11.3976) -> (-41.2478, 10.5752)
  line L114 (-42.0434, 12.2063) -> (-41.6314, 11.3976)
  line L115 (-42.4833, 13) -> (-42.0434, 12.2063)
  line L116 (-42.9507, 13.7779) -> (-42.4833, 13)
  line L117 (-43.445, 14.539) -> (-42.9507, 13.7779)
  line L118 (-43.9656, 15.2824) -> (-43.445, 14.539)
  line L119 (-44.5117, 16.0072) -> (-43.9656, 15.2824)
  line L120 (-45.0828, 16.7125) -> (-44.5117, 16.0072)
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extrude "Extrude14" cut sketch "Cam lateral service opening" along normal blind 12.2
work_plane "WorkPlane15" AlongDistance 36 ExtraOffset 0
sketch "Clear service path beneath sensor rails" plane through (36, 0, 0) normal (1, 0, 0) x axis (0, 0, -1)
  line L1 (-48.9, -18) -> (-48.9, -28)
  line L2 (-56, -18) -> (-48.9, -18)
  line L3 (-56, -28) -> (-56, -18)
  line L4 (-48.9, -28) -> (-56, -28)
extrude "Extrude15" cut sketch "Clear service path beneath sensor rails" along normal blind 44.1
work_plane "WorkPlane16" AlongDistance 36 ExtraOffset 0
sketch "Clear service path beneath sensor rails (1)" plane through (36, 0, 0) normal (1, 0, 0) x axis (0, 0, -1)
  line L1 (-48.9, 28) -> (-48.9, 18)
  line L2 (-56, 28) -> (-48.9, 28)
  line L3 (-56, 18) -> (-56, 28)
  line L4 (-48.9, 18) -> (-56, 18)
extrude "Extrude16" cut sketch "Clear service path beneath sensor rails (1)" along normal blind 44.1
work_plane "WorkPlane11" AlongDistance -24 ExtraOffset 0
sketch "Raise mount clear of rail bolt axes" plane through (-24, 0, 0) normal (1, 0, 0) x axis (0, 0, -1)
  line L1 (-52, -44) -> (-52, -66)
  line L2 (-57, -44) -> (-52, -44)
  line L3 (-57, -66) -> (-57, -44)
  line L4 (-52, -66) -> (-57, -66)
extrude "Extrude11" add sketch "Raise mount clear of rail bolt axes" along normal blind 48
work_plane "WorkPlane12" AlongDistance -24 ExtraOffset 0
sketch "Close old block mounting hole" plane through (-24, 0, 0) normal (1, 0, 0) x axis (0, 0, -1)
  circle C1 centre (-44, -59) radius 2.01
extrude "Extrude12" add sketch "Close old block mounting hole" along normal blind 8.7
work_plane "WorkPlane13" AlongDistance -24.1 ExtraOffset 0
sketch "Raised M3 block insert" plane through (-24.1, 0, 0) normal (1, 0, 0) x axis (0, 0, -1)
  circle C1 centre (-52, -59) radius 2
extrude "Extrude13" cut sketch "Raised M3 block insert" along normal blind 8.9
work_plane "WorkPlane14" AlongDistance 15.3 ExtraOffset 0
sketch "Close old block mounting hole (1)" plane through (15.3, 0, 0) normal (1, 0, 0) x axis (0, 0, -1)
  circle C1 centre (-44, -59) radius 2.01
extrude "Extrude14" add sketch "Close old block mounting hole (1)" along normal blind 8.7
work_plane "WorkPlane15" AlongDistance 15.2 ExtraOffset 0
sketch "Raised M3 block insert (1)" plane through (15.2, 0, 0) normal (1, 0, 0) x axis (0, 0, -1)
  circle C1 centre (-52, -59) radius 2
extrude "Extrude15" cut sketch "Raised M3 block insert (1)" along normal blind 8.9
work_plane "WorkPlane18" AlongDistance -36 ExtraOffset 0
sketch "Close old plate mounting hole" plane through (-36, 0, 0) normal (1, 0, 0) x axis (0, 0, -1)
  circle C1 centre (-44, -59) radius 1.71
extrude "Extrude18" add sketch "Close old plate mounting hole" along normal blind 12
work_plane "WorkPlane19" AlongDistance -36.1 ExtraOffset 0
sketch "Raised M3 block fastener" plane through (-36.1, 0, 0) normal (1, 0, 0) x axis (0, 0, -1)
  circle C1 centre (-52, -59) radius 1.7
extrude "Extrude19" cut sketch "Raised M3 block fastener" along normal blind 12.2
work_plane "WorkPlane17" AlongDistance 24 ExtraOffset 0
sketch "Close old plate mounting hole" plane through (24, 0, 0) normal (1, 0, 0) x axis (0, 0, -1)
  circle C1 centre (-44, -59) radius 1.71
extrude "Extrude17" add sketch "Close old plate mounting hole" along normal blind 12
work_plane "WorkPlane18" AlongDistance 23.9 ExtraOffset 0
sketch "Raised M3 block fastener" plane through (23.9, 0, 0) normal (1, 0, 0) x axis (0, 0, -1)
  circle C1 centre (-52, -59) radius 1.7
extrude "Extrude18" cut sketch "Raised M3 block fastener" along normal blind 12.2
work_plane "WorkPlane16" AlongDistance -24 ExtraOffset 0
sketch "Close old block mounting hole (2)" plane through (-24, 0, 0) normal (1, 0, 0) x axis (0, 0, -1)
  circle C1 centre (-44, -51) radius 2.01
extrude "Extrude16" add sketch "Close old block mounting hole (2)" along normal blind 8.7
work_plane "WorkPlane17" AlongDistance -24.1 ExtraOffset 0
sketch "Raised M3 block insert (2)" plane through (-24.1, 0, 0) normal (1, 0, 0) x axis (0, 0, -1)
  circle C1 centre (-52, -51) radius 2
extrude "Extrude17" cut sketch "Raised M3 block insert (2)" along normal blind 8.9
work_plane "WorkPlane18" AlongDistance 15.3 ExtraOffset 0
sketch "Close old block mounting hole (3)" plane through (15.3, 0, 0) normal (1, 0, 0) x axis (0, 0, -1)
  circle C1 centre (-44, -51) radius 2.01
extrude "Extrude18" add sketch "Close old block mounting hole (3)" along normal blind 8.7
work_plane "WorkPlane19" AlongDistance 15.2 ExtraOffset 0
sketch "Raised M3 block insert (3)" plane through (15.2, 0, 0) normal (1, 0, 0) x axis (0, 0, -1)
  circle C1 centre (-52, -51) radius 2
extrude "Extrude19" cut sketch "Raised M3 block insert (3)" along normal blind 8.9
work_plane "WorkPlane20" AlongDistance -36 ExtraOffset 0
sketch "Close old plate mounting hole (1)" plane through (-36, 0, 0) normal (1, 0, 0) x axis (0, 0, -1)
  circle C1 centre (-44, -51) radius 1.71
extrude "Extrude20" add sketch "Close old plate mounting hole (1)" along normal blind 12
work_plane "WorkPlane21" AlongDistance -36.1 ExtraOffset 0
sketch "Raised M3 block fastener (1)" plane through (-36.1, 0, 0) normal (1, 0, 0) x axis (0, 0, -1)
  circle C1 centre (-52, -51) radius 1.7
extrude "Extrude21" cut sketch "Raised M3 block fastener (1)" along normal blind 12.2
work_plane "WorkPlane19" AlongDistance 24 ExtraOffset 0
